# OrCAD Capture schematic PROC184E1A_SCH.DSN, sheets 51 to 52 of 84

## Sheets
51 56. USB HUB: size C; title: USB HUB; note: PROC184_SCH
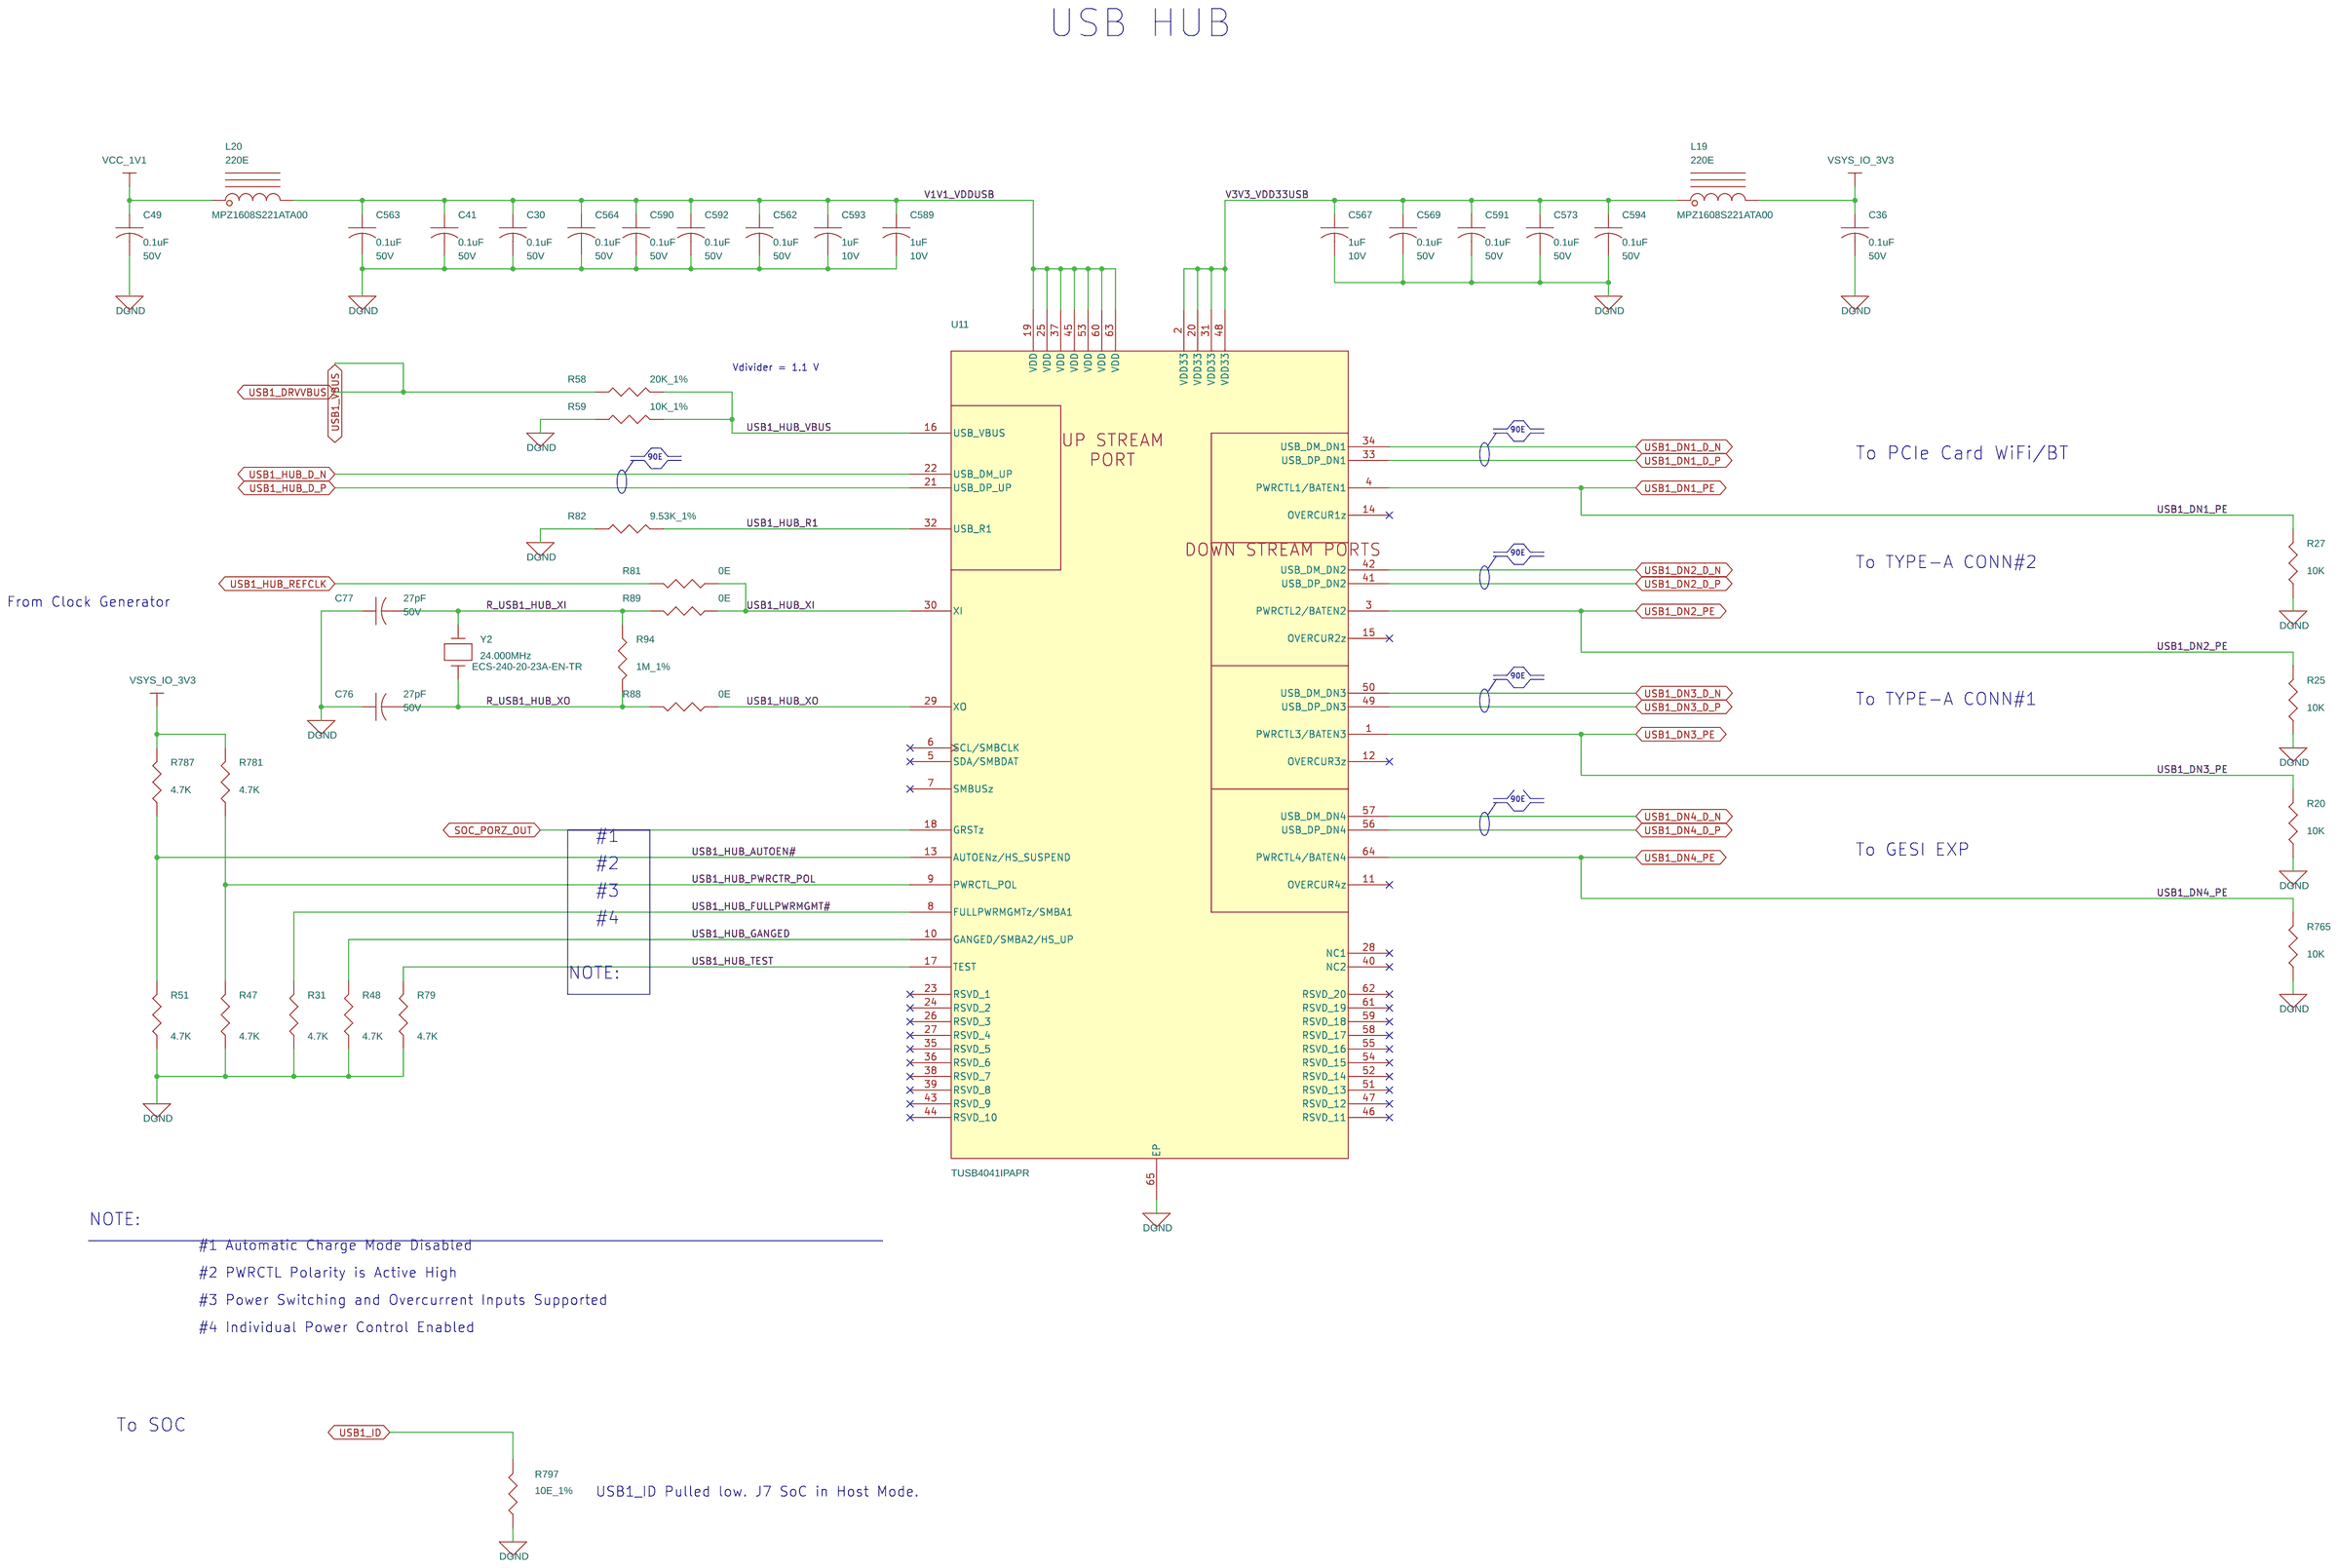
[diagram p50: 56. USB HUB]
52 57. USB 2.0 TYPE A CONN: size C; title: USB 2.0 TYPE-A CONNECTORS; note: PROC184_SCH
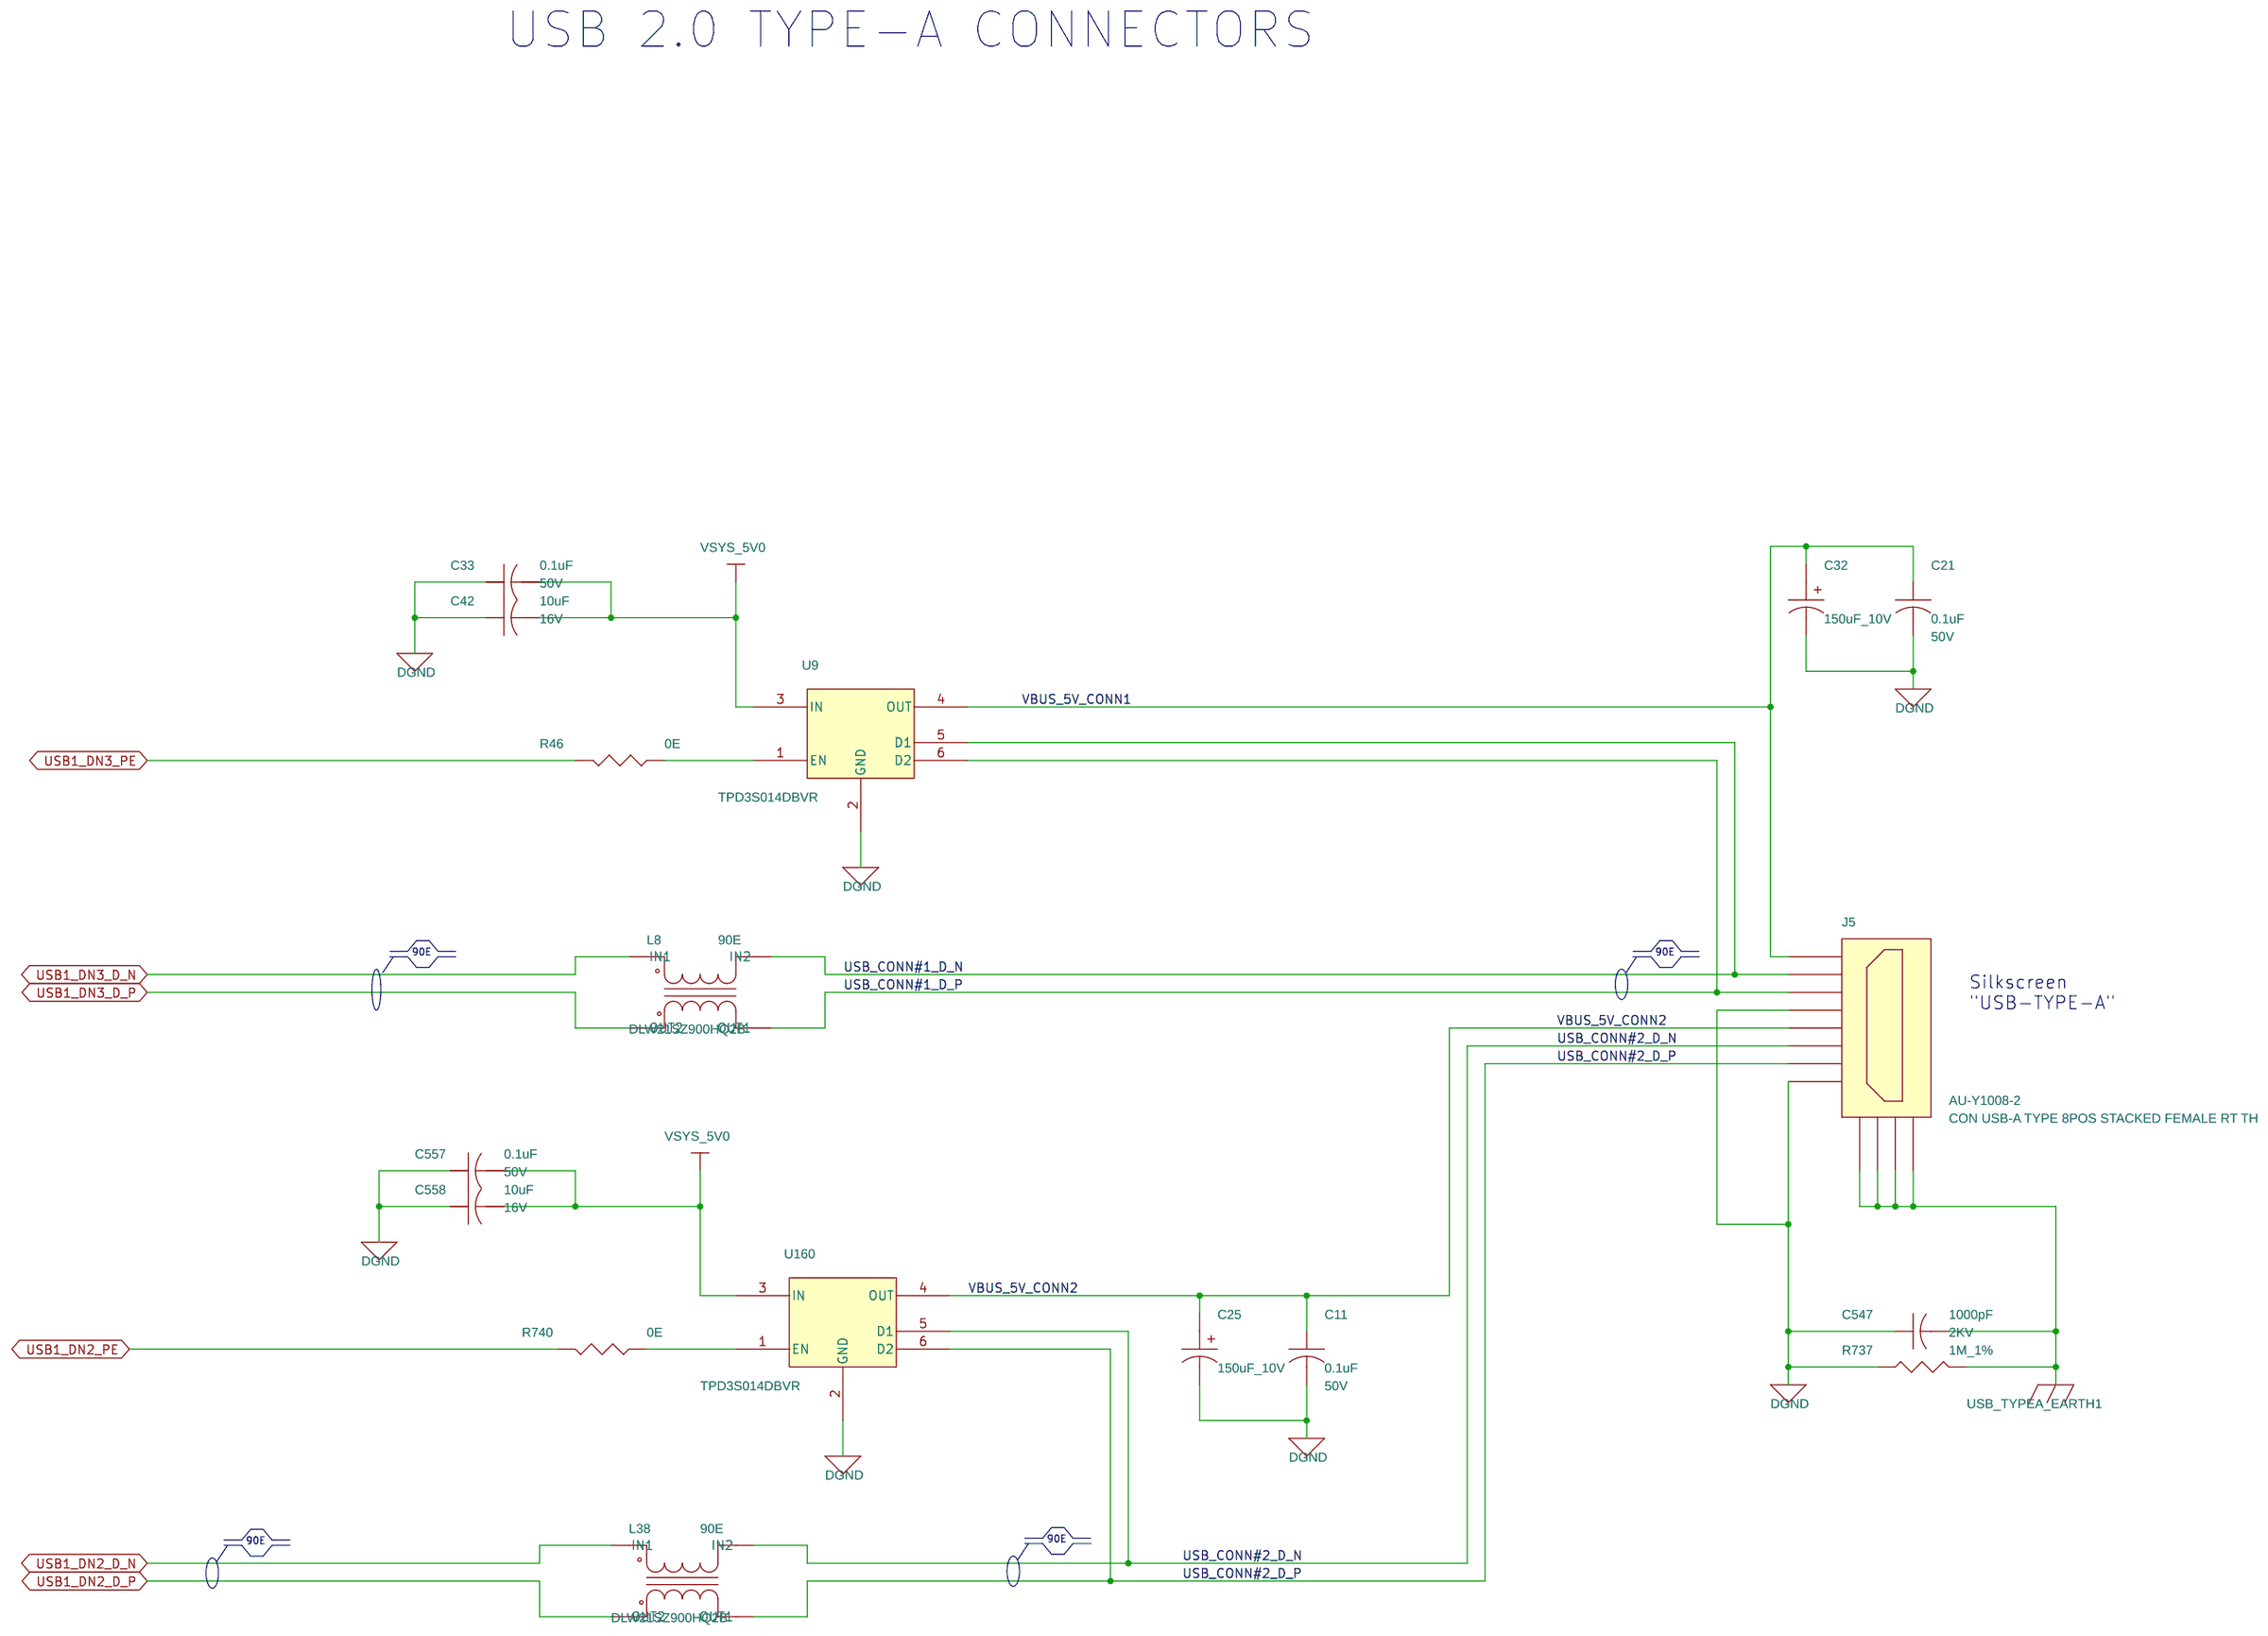
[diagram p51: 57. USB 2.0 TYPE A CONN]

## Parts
sheet 56. USB HUB
C30  0.1uF  [CAP0402_0-75]
C36  0.1uF  [CAP0402_0-75]
C41  0.1uF  [CAP0402_0-75]
C49  0.1uF  [CAP0402_0-75]
C76  27pF  [CAP0402_0-75]
C77  27pF  [CAP0402_0-75]
C562  0.1uF  [CAP0402_0-75]
C563  0.1uF  [CAP0402_0-75]
C564  0.1uF  [CAP0402_0-75]
C567  1uF  [CAP0402_0-75]
C569  0.1uF  [CAP0402_0-75]
C573  0.1uF  [CAP0402_0-75]
C589  1uF  [CAP0402_0-75]
C590  0.1uF  [CAP0402_0-75]
C591  0.1uF  [CAP0402_0-75]
C592  0.1uF  [CAP0402_0-75]
C593  1uF  [CAP0402_0-75]
C594  0.1uF  [CAP0402_0-75]
L19  220E  [IND0603_1]
L20  220E  [IND0603_1]
R20  10K  [RES0402_0-5]
R25  10K  [RES0402_0-5]
R27  10K  [RES0402_0-5]
R31  4.7K  [RES0402_0-5]
R47  4.7K  [RES0402_0-5]
R48  4.7K  [RES0402_0-5]
R51  4.7K  [RES0402_0-5]
R58  20K_1%  [RES0402_0-5]
R59  10K_1%  [RES0402_0-5]
R79  4.7K  [RES0402_0-5]
R81  0E  [RES0402_0-5]
R82  9.53K_1%  [RES0402_0-5]
R88  0E  [RES0402_0-5]
R89  0E  [RES0402_0-5]
R94  1M_1%  [RES0402_0-5]
R765  10K  [RES0402_0-5]
R781  4.7K  [RES0402_0-5]
R787  4.7K  [RES0402_0-5]
R797  10E_1%  [RES0402_0-5]
U11  TUSB4041IPAPR  [HTQFP64_TUSB4041I_400X400_1-2]
Y2  24.000MHz  [XTAL_ECX-64AEN_240X150_SMD_1-1]
sheet 57. USB 2.0 TYPE A CONN
C11  0.1uF  [CAP0402_0-75]
C21  0.1uF  [CAP0402_0-75]
C25  150uF_10V  [CAPT7343D_3-25]
C32  150uF_10V  [CAPT7343D_3-25]
C33  0.1uF  [CAP0402_0-75]
C42  10uF  [CAP0805_1-5]
C547  1000pF  [CAP1206_1-75]
C557  0.1uF  [CAP0402_0-75]
C558  10uF  [CAP0805_1-5]
J5  CON_USB-A_8_F  [CON_USBA8_AU-Y1008-2_S_R_T_15-5]
L8  90E  [IND4_DLW21H_90X60_SMD_1-4]
L38  90E  [IND4_DLW21H_90X60_SMD_1-4]
R46  0E  [RES0402_0-5]
R737  1M_1%  [RES0805_0-75]
R740  0E  [RES0402_0-5]
U9  TPD3S014DBVR  [SOT23-6_1-5]
U160  TPD3S014DBVR  [SOT23-6_1-5]

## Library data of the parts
C11 C21 C30 C33 C36 C41 C49 C557 C562-C564 C569 C573 C590-C592 C594 = CAP: CAP CERAMIC 0.1uF 50V 10% X7R 0402; Automotive Alternate_mfr_name: TDK; Automotive Alternate_mfr_part_number: CGA2B3X7R1H104K050BB; Chkd/date: MANIRAJA/261020; Crtd /date: ALVY/211020; Custom_Duty: 15%; Customs_HS_Code: 85322990; Direct Alternate_mfr_name: TDK; Direct Alternate_mfr_part_number: C1005X7R1H104K050BE; Distributor_name: DIGIKEY; Distributor_part_number: 490-10700-1-ND; Footprint Path: Y:\MIS_DATABASE\Library\ALTIUM_TOOL\PCB_FOOTPRINTS\Altium_Footprint_Lib.PcbLib; Height: 0.55MM; Library Path: Y:\MIS_DATABASE\Library\ALTIUM_TOOL\SCHEMATICS_PARTS\MS_DISCRETE_Library.schlib; Manufacturer: MURATA; Mfr_name: MURATA; Mfr_part_number: GRM155R71H104KE14D; Mistral Part No: 120011100014-R; Package: 0402; Part_type: CAPACITORS\CERAMIC; Project: J7_CP; RoHS: RoHS; Temperature: -55°C+125°C; Tolerance: 10%; Voltage: 50V; Wattage: NA; Weight: 3.1mg; Datasheet: Y:\MIS_DATABASE\DATASHEETS\CAPACITORS\GRM155R71H104KE14.PDF
C76 C77 = CAP: CAP CERAMIC 27pF 50V 5% C0G(NP0) 0402; Automotive Alternate_mfr_name: TDK; Automotive Alternate_mfr_part_number: CGA2B2C0G1H270J050BA; Chkd/date: MAZHAR/241208; Crtd /date: GEETHA/090606; Custom_Duty: 15%; Customs_HS_Code: 85322990; Direct Alternate_mfr_name: SAMSUNG; Direct Alternate_mfr_part_number: CL05C270JB5NNNC; Distributor_name: DIGIKEY; Distributor_part_number: 311-1019-1-ND; Footprint Path: Y:\MIS_DATABASE\Library\ALTIUM_TOOL\PCB_FOOTPRINTS\Altium_Footprint_Lib.PcbLib; Height: 0.55MM; Library Path: Y:\MIS_DATABASE\Library\ALTIUM_TOOL\SCHEMATICS_PARTS\MS_DISCRETE_Library.schlib; Manufacturer: YAGEO AMERICA; Mfr_name: YAGEO AMERICA; Mfr_part_number: CC0402JRNPO9BN270; Mistral Part No: 120014100024-R; Package: 0402; Part_type: CAPACITORS\CERAMIC; Project: PNAV; RoHS: RoHS; Temperature: -55°C+125°C; Tolerance: 5%; Voltage: 50V; Wattage: NA; Weight: 0.65mg; Datasheet: Y:\MIS_DATABASE\DATASHEETS\CAPACITORS\YACC-NPO.PDF
C567 C589 C593 = CAP: CAP CERAMIC 1uF 10V 10% X7S AUTO 0402; Automotive Alternate_mfr_name: TAIYO YUDEN; Automotive Alternate_mfr_part_number: EMK105BJ105KVHF; Chkd/date: MANIRAJA/100918; Crtd /date: ALVY/100918; Custom_Duty: 15%; Customs_HS_Code: 85322990; Direct Alternate_mfr_name: YAGEO AMERICA; Direct Alternate_mfr_part_number: CC0402KRX5R7BB105; Distributor_name: DIGIKEY; Distributor_part_number: 490-13409-1-ND; Footprint Path: Y:\MIS_DATABASE\Library\ALTIUM_TOOL\PCB_FOOTPRINTS\Altium_Footprint_Lib.PcbLib; Height: 0.70MM; Library Path: Y:\MIS_DATABASE\Library\ALTIUM_TOOL\SCHEMATICS_PARTS\MS_DISCRETE_Library.schlib; Manufacturer: TDK CORPORATION; Mfr_name: MURATA; Mfr_part_number: GCM155C71A105KE38D; Mistral Part No: 120018090021-R; Package: 0402; Part_type: CAPACITORS\CERAMIC; Project: SMART-M_SCRIPTALK_PB; RoHS: RoHS; Temperature: -55°C+125°C; Tolerance: 10%; Voltage: 10V; Wattage: NA; Weight: 6mg; Datasheet: Y:\MIS_DATABASE\DATASHEETS\CAPACITORS\MURATA-GCM-SER.PDF
L19 L20 = INDUCTOR_FERRITE: IND BEAD CHIP 220E 2.2A 25% 0603; Automotive Alternate_mfr_name: TDK; Automotive Alternate_mfr_part_number: MPZ1608S221ATD25; Chkd/date: MANIRAJA/130917; Crtd /date: USMAN/201108; Custom_Duty: 24%; Customs_HS_Code: 85437099; Direct Alternate_mfr_name: TDK; Direct Alternate_mfr_part_number: MPZ1608S221ATA00; Distributor_name: DIGIKEY; Distributor_part_number: 445-1565-1-ND; Height: 0.95MM; Manufacturer: TDK CORPORATION; Mfr_name: TDK CORPORATION; Mfr_part_number: MPZ1608S221ATA00; Mistral Part No: 130009030553-R; Package: 0603; Part_type: INDUCTOR; Project: KHAN_HSST; RoHS: RoHS; Temperature: -55°C+125°C; Tolerance: 25%; Voltage: NA; Wattage: NA; Weight: 4mg; Datasheet: Y:\MIS_DATABASE\DATASHEETS\DISCRETES\INDUCTORS\MPZ1608.PDF
R20 R25 R27 R765 = RESISTOR: RES 10K 1/16W 5% 0402; Chkd/date: VASANTHA/061216; Crtd /date: MAZHAR/230805; Custom_Duty: 15%; Customs_HS_Code: 85332119; Distributor_name: DIGIKEY; Distributor_part_number: 311-10KJRCT-ND; Footprint Path: Y:\MIS_DATABASE\Library\ALTIUM_TOOL\PCB_FOOTPRINTS\Altium_Footprint_Lib.PcbLib; Height: 0.40MM; Library Path: Y:\MIS_DATABASE\Library\ALTIUM_TOOL\SCHEMATICS_PARTS\MS_DISCRETE_Library.schlib; Manufacturer: YAGEO AMERICA; Mfr_name: YAGEO AMERICA; Mfr_part_number: RC0402JR-0710KL; Mistral Part No: 110011060021-R; Package: 0402; Part_type: RESISTORS\FIXED; Project: HSE; RoHS: RoHS; Temperature: -55°C+155°C; Tolerance: 5%; Voltage: NA; Wattage: 1/16W; Weight: 0.65mg; Datasheet: Y:\MIS_DATABASE\DATASHEETS\RESISTORS\RCXXXXL-SER_MAR18.PDF
R31 R48 R79 R781 R787 = RESISTOR: RES 4.7K 1/16W 5% 0402; Chkd/date: VASANTHA/130516; Crtd /date: VASANTHA/130516; Custom_Duty: 15%; Customs_HS_Code: 85332119; Distributor_name: DIGIKEY; Distributor_part_number: 311-4.7KJRCT-ND; Footprint Path: Y:\MIS_DATABASE\Library\ALTIUM_TOOL\PCB_FOOTPRINTS\Altium_Footprint_Lib.PcbLib; Height: 0.40MM; Library Path: Y:\MIS_DATABASE\Library\ALTIUM_TOOL\SCHEMATICS_PARTS\MS_DISCRETE_Library.schlib; Manufacturer: YAGEO AMERICA; Mfr_name: YAGEO AMERICA; Mfr_part_number: RC0402JR-074K7L; Mistral Part No: 110011060001-R; Package: 0402; Part_type: RESISTORS\FIXED; Project: TMDXCSK368; RoHS: RoHS; Temperature: -55°C+155°C; Tolerance: 5%; Voltage: NA; Wattage: 1/16W; Weight: 0.65mg; Datasheet: Y:\MIS_DATABASE\DATASHEETS\RESISTORS\RCXXXXL-SER_MAR18.PDF
R47 R51 = RESISTOR: RES 4.7K 1/16W 5% 0402; Assembly_Instruction: DNI; Chkd/date: VASANTHA/130516; Crtd /date: VASANTHA/130516; Custom_Duty: 15%; Customs_HS_Code: 85332119; Distributor_name: DIGIKEY; Distributor_part_number: 311-4.7KJRCT-ND; Footprint Path: Y:\MIS_DATABASE\Library\ALTIUM_TOOL\PCB_FOOTPRINTS\Altium_Footprint_Lib.PcbLib; Height: 0.40MM; Library Path: Y:\MIS_DATABASE\Library\ALTIUM_TOOL\SCHEMATICS_PARTS\MS_DISCRETE_Library.schlib; Manufacturer: YAGEO AMERICA; Mfr_name: YAGEO AMERICA; Mfr_part_number: RC0402JR-074K7L; Mistral Part No: 110011060001-R; Package: 0402; Part_type: RESISTORS\FIXED; Project: TMDXCSK368; RoHS: RoHS; Temperature: -55°C+155°C; Tolerance: 5%; Voltage: NA; Wattage: 1/16W; Weight: 0.65mg; Datasheet: Y:\MIS_DATABASE\DATASHEETS\RESISTORS\RCXXXXL-SER_MAR18.PDF
R58 = RESISTOR: RES 20K 1/16W 1% 0402; Chkd/date: MAZHAR/280108; Crtd /date: USMAN/280108; Custom_Duty: 15%; Customs_HS_Code: 85332119; Distributor_name: DIGIKEY; Distributor_part_number: 311-20.0KLRCT-ND; Footprint Path: Y:\MIS_DATABASE\Library\ALTIUM_TOOL\PCB_FOOTPRINTS\Altium_Footprint_Lib.PcbLib; Height: 0.40MM; Library Path: Y:\MIS_DATABASE\Library\ALTIUM_TOOL\SCHEMATICS_PARTS\MS_DISCRETE_Library.schlib; Manufacturer: YAGEO AMERICA; Mfr_name: YAGEO AMERICA; Mfr_part_number: RC0402FR-0720KL; Mistral Part No: 110009030486-R; Package: 0402; Part_type: RESISTORS\FIXED; Project: TELEMETRY ENCODER; RoHS: RoHS; Temperature: -55°C+155°C; Tolerance: 1%; Voltage: NA; Wattage: 1/16W; Weight: 0.65mg; Datasheet: Y:\MIS_DATABASE\DATASHEETS\RESISTORS\RCXXXXL-SER_MAR18.PDF
R59 = RESISTOR: RES 10K 1/16W 1% 0402; Chkd/date: VASANTHA/201216; Crtd /date: GEETHA/290506; Custom_Duty: 15%; Customs_HS_Code: 85332119; Distributor_name: DIGIKEY; Distributor_part_number: 311-10.0KLRTR-ND; Footprint Path: Y:\MIS_DATABASE\Library\ALTIUM_TOOL\PCB_FOOTPRINTS\Altium_Footprint_Lib.PcbLib; Height: 0.40MM; Library Path: Y:\MIS_DATABASE\Library\ALTIUM_TOOL\SCHEMATICS_PARTS\MS_DISCRETE_Library.schlib; Manufacturer: YAGEO AMERICA; Mfr_name: YAGEO AMERICA; Mfr_part_number: RC0402FR-0710KL; Mistral Part No: 110015090015-R; Package: 0402; Part_type: RESISTORS\FIXED; Project: VOCERA; RoHS: RoHS; Temperature: -55°C+155°C; Tolerance: 1%; Voltage: NA; Wattage: 1/16W; Weight: 0.65mg; Datasheet: Y:\MIS_DATABASE\DATASHEETS\RESISTORS\RCXXXXL-SER_MAR18.PDF
R81 = RESISTOR: RES 0E 1/10W JUMPER 0402; Assembly_Instruction: DNI; Chkd/date: VASANTHA/061216; Crtd /date: NAVEED/201014; Custom_Duty: 15%; Customs_HS_Code: 85332119; Distributor_name: DIGIKEY; Distributor_part_number: P0.0JCT-ND; Footprint Path: Y:\MIS_DATABASE\Library\ALTIUM_TOOL\PCB_FOOTPRINTS\Altium_Footprint_Lib.PcbLib; Height: 0.40MM; IBISSP_MODLES: VALUE REPEATING 2 TIME; Library Path: Y:\MIS_DATABASE\Library\ALTIUM_TOOL\SCHEMATICS_PARTS\MS_DISCRETE_Library.schlib; Manufacturer: PANASONIC-ECG; Mfr_name: PANASONIC-ECG; Mfr_part_number: ERJ-2GE0R00X; Mistral Part No: 110018030052-R; Package: 0402; Part_type: RESISTORS\FIXED; Project: AEGIS POM; RoHS: RoHS; Temperature: -55°C+155°C; Tolerance: NA; Voltage: NA; Wattage: 1/10W; Weight: 0.8mg; Datasheet: Y:\MIS_DATABASE\DATASHEETS\RESISTORS\PAN-ERJSER_NOV17.PDF
R82 = RESISTOR: RES 9.53K 1/10W 1% 0402; Chkd/date: MAZHAR/101110; Crtd /date: BAVISH/091110; Custom_Duty: 15%; Customs_HS_Code: 85332119; Distributor_name: DIGIKEY; Distributor_part_number: P9.53KLCT-ND; Footprint Path: Y:\MIS_DATABASE\Library\ALTIUM_TOOL\PCB_FOOTPRINTS\Altium_Footprint_Lib.PcbLib; Height: 0.40MM; Library Path: Y:\MIS_DATABASE\Library\ALTIUM_TOOL\SCHEMATICS_PARTS\MS_DISCRETE_Library.schlib; Manufacturer: PANASONIC-ECG; Mfr_name: PANASONIC-ECG; Mfr_part_number: ERJ-2RKF9531X; Mistral Part No: 110010110003-R; Package: 0402; Part_type: RESISTORS\FIXED; Project: CPCI3GADC_CARD; RoHS: RoHS; Temperature: -55°C+155°C; Tolerance: 1%; Voltage: NA; Wattage: 1/10W; Weight: 0.8mg; Datasheet: Y:\MIS_DATABASE\DATASHEETS\RESISTORS\PAN-ERJSER_NOV17.PDF
R46 R88 R89 R740 = RESISTOR: RES 0E 1/10W JUMPER 0402; Chkd/date: VASANTHA/061216; Crtd /date: NAVEED/201014; Custom_Duty: 15%; Customs_HS_Code: 85332119; Distributor_name: DIGIKEY; Distributor_part_number: P0.0JCT-ND; Footprint Path: Y:\MIS_DATABASE\Library\ALTIUM_TOOL\PCB_FOOTPRINTS\Altium_Footprint_Lib.PcbLib; Height: 0.40MM; IBISSP_MODLES: VALUE REPEATING 2 TIME; Library Path: Y:\MIS_DATABASE\Library\ALTIUM_TOOL\SCHEMATICS_PARTS\MS_DISCRETE_Library.schlib; Manufacturer: PANASONIC-ECG; Mfr_name: PANASONIC-ECG; Mfr_part_number: ERJ-2GE0R00X; Mistral Part No: 110018030052-R; Package: 0402; Part_type: RESISTORS\FIXED; Project: AEGIS POM; RoHS: RoHS; Temperature: -55°C+155°C; Tolerance: NA; Voltage: NA; Wattage: 1/10W; Weight: 0.8mg; Datasheet: Y:\MIS_DATABASE\DATASHEETS\RESISTORS\PAN-ERJSER_NOV17.PDF
R94 = RESISTOR: RES 1M 1/10W 1% 0402; Chkd/date: VASANTHA/291216; Crtd /date: MAZHAR/110210; Custom_Duty: 15%; Customs_HS_Code: 85332119; Distributor_name: DIGIKEY; Distributor_part_number: P1.00MLCT-ND; Footprint Path: Y:\MIS_DATABASE\Library\ALTIUM_TOOL\PCB_FOOTPRINTS\Altium_Footprint_Lib.PcbLib; Height: 0.40MM; Library Path: Y:\MIS_DATABASE\Library\ALTIUM_TOOL\SCHEMATICS_PARTS\MS_DISCRETE_Library.schlib; Manufacturer: PANASONIC-ECG; Mfr_name: PANASONIC-ECG; Mfr_part_number: ERJ-2RKF1004X; Mistral Part No: 110010020012-R; Package: 0402; Part_type: RESISTORS\FIXED; Project: KOPIN_MODULS; RoHS: RoHS; Temperature: -55°C+155°C; Tolerance: 1%; Voltage: NA; Wattage: 1/10W; Weight: 0.8mg; Datasheet: Y:\MIS_DATABASE\DATASHEETS\RESISTORS\PAN-ERJSER_NOV17.PDF
R797 = RESISTOR: RES 10E 1/10W 1% 0402; Chkd/date: VASANTHA/201216; Crtd /date: MAZHAR/120505; Custom_Duty: 15%; Customs_HS_Code: 85332119; Distributor_name: DIGIKEY; Distributor_part_number: P10.0LCT-ND; Footprint Path: Y:\MIS_DATABASE\Library\ALTIUM_TOOL\PCB_FOOTPRINTS\Altium_Footprint_Lib.PcbLib; Height: 0.40MM; Library Path: Y:\MIS_DATABASE\Library\ALTIUM_TOOL\SCHEMATICS_PARTS\MS_DISCRETE_Library.schlib; Manufacturer: PANASONIC-ECG; Mfr_name: PANASONIC-ECG; Mfr_part_number: ERJ-2RKF10R0X; Mistral Part No: 110009030203-R; Package: 0402; Part_type: RESISTORS\FIXED; Project: CTP02_REVA_BASE; RoHS: RoHS; Temperature: -55°C+155°C; Tolerance: 1%; Voltage: NA; Wattage: 1/10W; Weight: 0.8mg; Datasheet: Y:\MIS_DATABASE\DATASHEETS\RESISTORS\PAN-ERJSER_NOV17.PDF
U11 = TUSB4041IPAPQ1_HTQFP64_TI: IC FOUR PORT USB 2.0 HUB HTQFP64; Automotive Alternate_mfr_name: TEXAS INSTRUMENTS; Automotive Alternate_mfr_part_number: TUSB4041IPAPRQ1; Chkd/date: MANIRAJA/161018; Crtd /date: ALVY/161018; Custom_Duty: 15%; Customs_HS_Code: 85423100; Distributor_name: DIGIKEY; Distributor_part_number: 296-43143-1-ND; Footprint Path: Y:\MIS_DATABASE\Library\ALTIUM_TOOL\PCB_FOOTPRINTS\Altium_Footprint_Lib.PcbLib; Height: 1.20MM; Library Path: Y:\MIS_DATABASE\Library\ALTIUM_TOOL\SCHEMATICS_PARTS\MS_MISCINTERFACE_Library.schlib; Library Ref: TUSB4041IPAPQ1_HTQFP64; Manufacturer: TEXAS INSTRUMENTS; Mfr_name: TEXAS INSTRUMENTS; Mistral Part No: 141018100013-R; Package: HTQFP64; Part_type: ICS\INTERFACE; Project: TI_J7ES_EVM_CP; RoHS: RoHS; Temperature: -40°C+85°C; Tolerance: NA; Voltage: NA; Wattage: NA; Weight: 496.3mg; Datasheet: Y:\MIS_DATABASE\DATASHEETS\ICS\INTERFACE\TUSB4041I.PDF
Y2 = CRY: CRY 24.000MHz 20pF SMD; Chkd/date: MANIRAJA/220818; Crtd /date: CHAITHANYA/171111; Custom_Duty: 24%; Customs_HS_Code: 85439000; Distributor_name: DIGIKEY; Distributor_part_number: XC990CT-ND; Footprint Path: Y:\MIS_DATABASE\Library\ALTIUM_TOOL\PCB_FOOTPRINTS\Altium_Footprint_Lib.PcbLib; Height: 1.10MM; Library Path: Y:\MIS_DATABASE\Library\ALTIUM_TOOL\SCHEMATICS_PARTS\MS_DISCRETE_Library.schlib; Manufacturer: ECS INC; Mfr_name: ECS INC; Mfr_part_number: ECS-240-20-23A-EN-TR; Mistral Part No: 130011110044-R; Package: SMD; Part_type: CRYSTAL; Project: ACRO_DM3730; RoHS: RoHS; Temperature: -40°C+85°C; Tolerance: NA; Voltage: NA; Wattage: NA; Weight: 60mg; Datasheet: Y:\MIS_DATABASE\DATASHEETS\MISC\CRY_OSC\ECX-64XEN.PDF
C25 C32 = CAP_POL: CAP TANTALUM 150uF 10V 10% ESR 0.9E D7343; Chkd/date: MANIRAJA/240118; Crtd /date: MANIRAJA/240118; Custom_Duty: 15%; Customs_HS_Code: 85322990; Distributor_name: DIGIKEY; Distributor_part_number: 478-11241-1-ND; Footprint Path: Y:\MIS_DATABASE\Library\ALTIUM_TOOL\PCB_FOOTPRINTS\Altium_Footprint_Lib.PcbLib; Height: 3.10MM; Library Path: Y:\MIS_DATABASE\Library\ALTIUM_TOOL\SCHEMATICS_PARTS\MS_DISCRETE_Library.schlib; Manufacturer: AVX CORPORATION; Mfr_name: AVX CORPORATION; Mfr_part_number: TAJD157K010TNJV; Mistral Part No: 120018010025-R; Package: D7343; Part_type: CAPACITORS\TANTALUM; Project: TI_MAXIE_CPB; RoHS: RoHS; Temperature: -55°C+125°C; Tolerance: 10%; Voltage: 10V; Wattage: NA; Weight: 670mg; Datasheet: Y:\MIS_DATABASE\DATASHEETS\CAPACITORS\AVX-TAJ-SER.PDF
C42 C558 = CAP: CAP CERAMIC 10uF 16V 10% X5R 0805; Automotive Alternate_mfr_name: TDK; Automotive Alternate_mfr_part_number: CGA4J1X7S1C106K125AC; Chkd/date: SHREESHAIL/220506; Crtd /date: MAZHAR/150506; Custom_Duty: 15%; Customs_HS_Code: 85322990; Direct Alternate_mfr_name: TDK; Direct Alternate_mfr_part_number: C2012X7S1C106K125AC; Distributor_name: DIGIKEY; Distributor_part_number: 490-3886-1-ND; Footprint Path: Y:\MIS_DATABASE\Library\ALTIUM_TOOL\PCB_FOOTPRINTS\Altium_Footprint_Lib.PcbLib; Height: 1.35MM; Library Path: Y:\MIS_DATABASE\Library\ALTIUM_TOOL\SCHEMATICS_PARTS\MS_DISCRETE_Library.schlib; Manufacturer: MURATA; Mfr_name: MURATA; Mfr_part_number: GRM21BR61C106KE15L; Mistral Part No: 120009030205-R; Package: 0805; Part_type: CAPACITORS\CERAMIC; Project: VOCERA; RoHS: RoHS; Temperature: -55°C+85°C; Tolerance: 10%; Voltage: 16V; Wattage: NA; Weight: 9.5mg; Datasheet: Y:\MIS_DATABASE\DATASHEETS\CAPACITORS\MURATA-GXX-SER_NOV17.PDF
C547 = CAP: CAP CERAMIC 1000pF 2KV 10% X7R 1206; Automotive Alternate_mfr_name: KEMET; Automotive Alternate_mfr_part_number: C1206X102KGRACAUTO; Chkd/date: SHREESHAIL/291106; Crtd /date: MAZHAR/281106; Custom_Duty: 15%; Customs_HS_Code: 85322990; Direct Alternate_mfr_name: KEMET; Direct Alternate_mfr_part_number: C1206C102KGRACTU; Distributor_name: DIGIKEY; Distributor_part_number: 478-2956-1-ND; Footprint Path: Y:\MIS_DATABASE\Library\ALTIUM_TOOL\PCB_FOOTPRINTS\Altium_Footprint_Lib.PcbLib; Height: 1.52MM; Library Path: Y:\MIS_DATABASE\Library\ALTIUM_TOOL\SCHEMATICS_PARTS\MS_DISCRETE_Library.schlib; Manufacturer: AVX CORPORATION; Mfr_name: AVX CORPORATION; Mfr_part_number: 1206GC102KAT1A; Mistral Part No: 120015080006-R; Package: 1206; Part_type: CAPACITORS\CERAMIC; Project: ADR1B; RoHS: RoHS; Temperature: -55°C+125°C; Tolerance: 10%; Voltage: 2KV; Wattage: NA; Weight: 16.2mg; Datasheet: Y:\MIS_DATABASE\DATASHEETS\CAPACITORS\AVX_HV-MLC.PDF
J5 = CON_USB-A_8: CON USB-A TYPE 8POS STACKED FEMALE RT TH; Chkd/date: MANIRAJA/260218; Crtd /date: ALVY/260218; Custom_Duty: 24%; Customs_HS_Code: 85369090; Distributor_name: DIGIKEY; Distributor_part_number: AE11131-ND; Footprint Path: Y:\MIS_DATABASE\Library\ALTIUM_TOOL\PCB_FOOTPRINTS\Altium_Footprint_Lib.PcbLib; Height: 15.45MM; Library Path: Y:\MIS_DATABASE\Library\ALTIUM_TOOL\SCHEMATICS_PARTS\MS_CONNECTOR_Library.schlib; Manufacturer: ASSMANN ELECTRONICS; Mfr_name: ASSMANN ELECTRONICS; Mfr_part_number: AU-Y1008-2; Mistral Part No: 150018020023-R; Package: THRU-HOLE; Part_type: CONNECTOR\USB; Project: GRACO SMART MODULE; RoHS: RoHS; Temperature: -55°C+85°C; Tolerance: NA; Voltage: NA; Wattage: NA; Weight: NA; Datasheet: Y:\MIS_DATABASE\DATASHEETS\CONNECTORS\AU-Y1008-2.PDF
L8 L38 = INDUCTOR_DLW31S: IND COMMON MODE CHOKE 90E 280mA SMD; Chkd/date: MANIRAJA/270619; Crtd /date: MANIRAJA/270619; Custom_Duty: 24%; Customs_HS_Code: 85437099; Distributor_name: NA; Distributor_part_number: NA; Footprint Path: Y:\MIS_DATABASE\Library\ALTIUM_TOOL\PCB_FOOTPRINTS\Altium_Footprint_Lib.PcbLib; Height: 1.40MM; Library Path: Y:\MIS_DATABASE\Library\ALTIUM_TOOL\SCHEMATICS_PARTS\MS_DISCRETE_Library.schlib; Manufacturer: MURATA; Mfr_name: MURATA; Mfr_part_number: DLW21SZ900HQ2B; Mistral Part No: 130019060035-R; Package: SMD; Part_type: INDUCTOR; Project: TI_J7ES_CP; RoHS: RoHS; Temperature: -40°C+105°C; Tolerance: NA; Voltage: NA; Wattage: NA; Weight: 11mg; Datasheet: Y:\MIS_DATABASE\DATASHEETS\DISCRETES\INDUCTORS\DLW21SZ900HQ2B.PDF
R737 = RESISTOR: RES 1M 1/8W 1% 0805; Chkd/date: VASANTHA/150514; Crtd /date: BALACHANDAR/150514; Custom_Duty: 15%; Customs_HS_Code: 85332119; Distributor_name: DIGIKEY; Distributor_part_number: P1.00MCCT-ND; Footprint Path: Y:\MIS_DATABASE\Library\ALTIUM_TOOL\PCB_FOOTPRINTS\Altium_Footprint_Lib.PcbLib; Height: 0.70MM; Library Path: Y:\MIS_DATABASE\Library\ALTIUM_TOOL\SCHEMATICS_PARTS\MS_DISCRETE_Library.schlib; Manufacturer: PANASONIC-ECG; Mfr_name: PANASONIC-ECG; Mfr_part_number: ERJ-6ENF1004V; Mistral Part No: 110014100002-R; Package: 0805; Part_type: RESISTORS\FIXED; Project: HUMANWARE_PHOENIX; RoHS: RoHS; Temperature: -55°C+155°C; Tolerance: 1%; Voltage: NA; Wattage: 1/8W; Weight: 4mg; Datasheet: Y:\MIS_DATABASE\DATASHEETS\RESISTORS\PAN-ERJSER_NOV17.PDF
U9 U160 = TPD3S014D_SOT23-6: IC ESD PROTECTION FOR USB PORT WITH CURRENT LIMIT SWITCH SOT23-6; Chkd/date: VASANTHA/100217; Crtd /date: MANIRAJA/090217; Custom_Duty: 15%; Customs_HS_Code: 85423100; Distributor_name: DIGIKEY; Distributor_part_number: 296-38835-1-ND; Height: 1.45MM; Manufacturer: TEXAS INSTRUMENTS; Mfr_name: TEXAS INSTRUMENTS; Mistral Part No: 141017020013-R; Package: SOT23-6; Part_type: ICS\INTERFACE; Project: SD820_NANO_SOM; RoHS: RoHS; Temperature: -40°C+85°C; Tolerance: NA; Voltage: NA; Wattage: NA; Weight: 36mg; Datasheet: Y:\MIS_DATABASE\DATASHEETS\ICS\INTERFACE\TPD3S014XX.PDF

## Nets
DGND: C11.2 C21.2 C25.2 C30.2 C32.2 C33.1 C36.2 C41.2 C42.1 C49.2 C76.1 C77.1 C547.1 C557.1 C558.1 C562.2 C563.2 C564.2 C567.2 C569.2 C573.2 C589.2 C590.2 C591.2 C592.2 C593.2 C594.2 J5.4 J5.8 R20.1 R25.1 R27.1 R31.1 R47.1 R48.1 R51.1 R59.1 R79.1 R82.1 R737.1 R765.1 R797.1 U9.2(GND) U11.65(EP) U160.2(GND) ; also on sheet 11 12 13 14 15 16 17 18 20 21 22 23 24 25 26 27 28 29 30 31 32 33 34 35 36 37 38 39 40 41 42 43 44 45 46 47 48 49 50 53 54 55 56 57 58 59 60 61 62 63 64 65 66 67 68 69 70 71 72 73 76 77 78 79 81 82 83 84
V1V1_VDDUSB: C30.1 C41.1 C562.1 C563.1 C564.1 C589.1 C590.1 C592.1 C593.1 L20.2 U11.19(VDD) U11.25(VDD) U11.37(VDD) U11.45(VDD) U11.53(VDD) U11.60(VDD) U11.63(VDD)
V3V3_VDD33USB: C567.1 C569.1 C573.1 C591.1 C594.1 L19.1 U11.2(VDD33) U11.20(VDD33) U11.31(VDD33) U11.48(VDD33)
VBUS_5V_CONN1: C21.1 C32.1 J5.1 U9.4(OUT)
VBUS_5V_CONN2: C11.1 C25.1 J5.5 U160.4(OUT)
VCC_1V1: C49.1 L20.1 ; also on sheet 56 68
R_USB1_HUB_XI: C77.2 R89.2 R94.1 Y2.2
R_USB1_HUB_XO: C76.2 R88.2 R94.2 Y2.1
SOC_PORZ_OUT: U11.18(GRSTz) ; also on sheet 18 30 32 37 43 56 59 60 62 69
USB1_DN1_D_N: U11.34(USB_DM_DN1) ; also on sheet 59
USB1_DN1_D_P: U11.33(USB_DP_DN1) ; also on sheet 59
USB1_DN1_PE: R27.2 U11.4(PWRCTL1/BATEN1) ; also on sheet 59
USB1_DN2_D_N: L38.1(IN1) U11.42(USB_DM_DN2)
USB1_DN2_D_P: L38.4(OUT2) U11.41(USB_DP_DN2)
USB1_DN2_PE: R25.2 R740.2 U11.3(PWRCTL2/BATEN2)
USB1_DN3_D_N: L8.1(IN1) U11.50(USB_DM_DN3)
USB1_DN3_D_P: L8.4(OUT2) U11.49(USB_DP_DN3)
USB1_DN3_PE: R20.2 R46.2 U11.1(PWRCTL3/BATEN3)
USB1_DN4_D_N: U11.57(USB_DM_DN4) ; also on sheet 30
USB1_DN4_D_P: U11.56(USB_DP_DN4) ; also on sheet 30
USB1_DN4_PE: R765.2 U11.64(PWRCTL4/BATEN4) ; also on sheet 30
USB1_DRVVBUS: R58.1 ; also on sheet 24
USB1_HUB_AUTOEN#: R51.2 R787.1 U11.13(AUTOENz/HS_SUSPEND)
USB1_HUB_D_N: U11.22(USB_DM_UP) ; also on sheet 24
USB1_HUB_D_P: U11.21(USB_DP_UP) ; also on sheet 24
USB1_HUB_FULLPWRMGMT#: R31.2 U11.8(FULLPWRMGMTz/SMBA1)
USB1_HUB_GANGED: R48.2 U11.10(GANGED/SMBA2/HS_UP)
USB1_HUB_PWRCTR_POL: R47.2 R781.1 U11.9(PWRCTL_POL)
USB1_HUB_R1: R82.2 U11.32(USB_R1)
USB1_HUB_REFCLK: R81.2 ; also on sheet 34
USB1_HUB_TEST: R79.2 U11.17(TEST)
USB1_HUB_VBUS: R58.2 R59.2 U11.16(USB_VBUS)
USB1_HUB_XI: R81.1 R89.1 U11.30(XI)
USB1_HUB_XO: R88.1 U11.29(XO)
USB1_ID: R797.2 ; also on sheet 24
USB_CONN#1_D_N: J5.2 L8.2(IN2) U9.5(D1)
USB_CONN#1_D_P: J5.3 L8.3(OUT1) U9.6(D2)
USB_CONN#2_D_N: J5.6 L38.2(IN2) U160.5(D1)
USB_CONN#2_D_P: J5.7 L38.3(OUT1) U160.6(D2)
USB_TYPEA_EARTH1: C547.2 J5.SH1 J5.SH2 J5.SH3 J5.SH4 R737.2
VSYS_5V0: C33.2 C42.2 C557.2 C558.2 U9.3(IN) U160.3(IN) ; also on sheet 20 30 31 50 59 65 68 72 81 82 83 84
VSYS_IO_3V3: C36.1 L19.2 R781.2 R787.2 ; also on sheet 18 20 22 24 29 30 31 32 33 35 36 37 38 40 41 42 43 45 46 48 50 53 56 57 58 59 60 61 65 66 68 75 81 82
N24026991: R46.1 U9.1(EN)
N24026992: R740.1 U160.1(EN)

Not connected (* = marked no-connect by the designer): U11 5(SDA/SMBDAT)* 6(SCL/SMBCLK)* 7(SMBUSz)* 11(OVERCUR4z)* 12(OVERCUR3z)* 14(OVERCUR1z)* 15(OVERCUR2z)* 23(RSVD_1)* 24(RSVD_2)* 26(RSVD_3)* 27(RSVD_4)* 28(NC1)* 35(RSVD_5)* 36(RSVD_6)* 38(RSVD_7)* 39(RSVD_8)* 40(NC2)* 43(RSVD_9)* 44(RSVD_10)* 46(RSVD_11)* 47(RSVD_12)* 51(RSVD_13)* 52(RSVD_14)* 54(RSVD_15)* 55(RSVD_16)* 58(RSVD_17)* 59(RSVD_18)* 61(RSVD_19)* 62(RSVD_20)*

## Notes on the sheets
sheet 51
- USB HUB
- Vdivider = 1.1 V
- 90E
- 90E
- To PCIe Card WiFi/BT
- 90E
- To TYPE-A CONN#2
- From Clock Generator
- 90E
- To TYPE-A CONN#1
- 90E
- #1
- To GESI EXP
- #2
- #3
- #4
- NOTE:
- NOTE:
- #1 Automatic Charge Mode Disabled
- #2 PWRCTL Polarity is Active High
- #3 Power Switching and Overcurrent Inputs Supported
- #4 Individual Power Control Enabled
- To SOC
- USB1_ID Pulled low. J7 SoC in Host Mode.
sheet 52
- USB 2.0 TYPE-A CONNECTORS
- 90E
- 90E
- Silkscreen
  "USB-TYPE-A"
- 90E
- 90E
